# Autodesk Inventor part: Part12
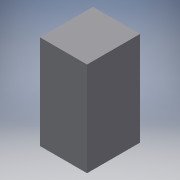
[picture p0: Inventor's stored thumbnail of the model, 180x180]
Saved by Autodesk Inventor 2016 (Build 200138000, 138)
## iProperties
Created: 2020-04
Part Number: Part12
Material: Generic
Document SubType Name: Modeling
Designer: merlin
Density: 1 g/cm^3
Appearance: Default
Author: merlin
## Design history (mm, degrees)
node "3D Sketch1"
sketch "Sketch1"
  geometry: L1 (-109.537, -117.475)-(-122.237, -117.475); L2 (-122.237, -117.475)-(-122.237, -131.762); L3 (-122.237, -131.762)-(-109.537, -131.762); L4 (-109.537, -131.762)-(-109.537, -117.475); 1 further point
  constraints: 8 end point, 2 parallel, 1 horizontal, 1 perpendicular
extrude "Extrusion1" new body sketch "Sketch1" distance "d0" = 25.4; taper "d1" = 0 deg
body "Solid1"
